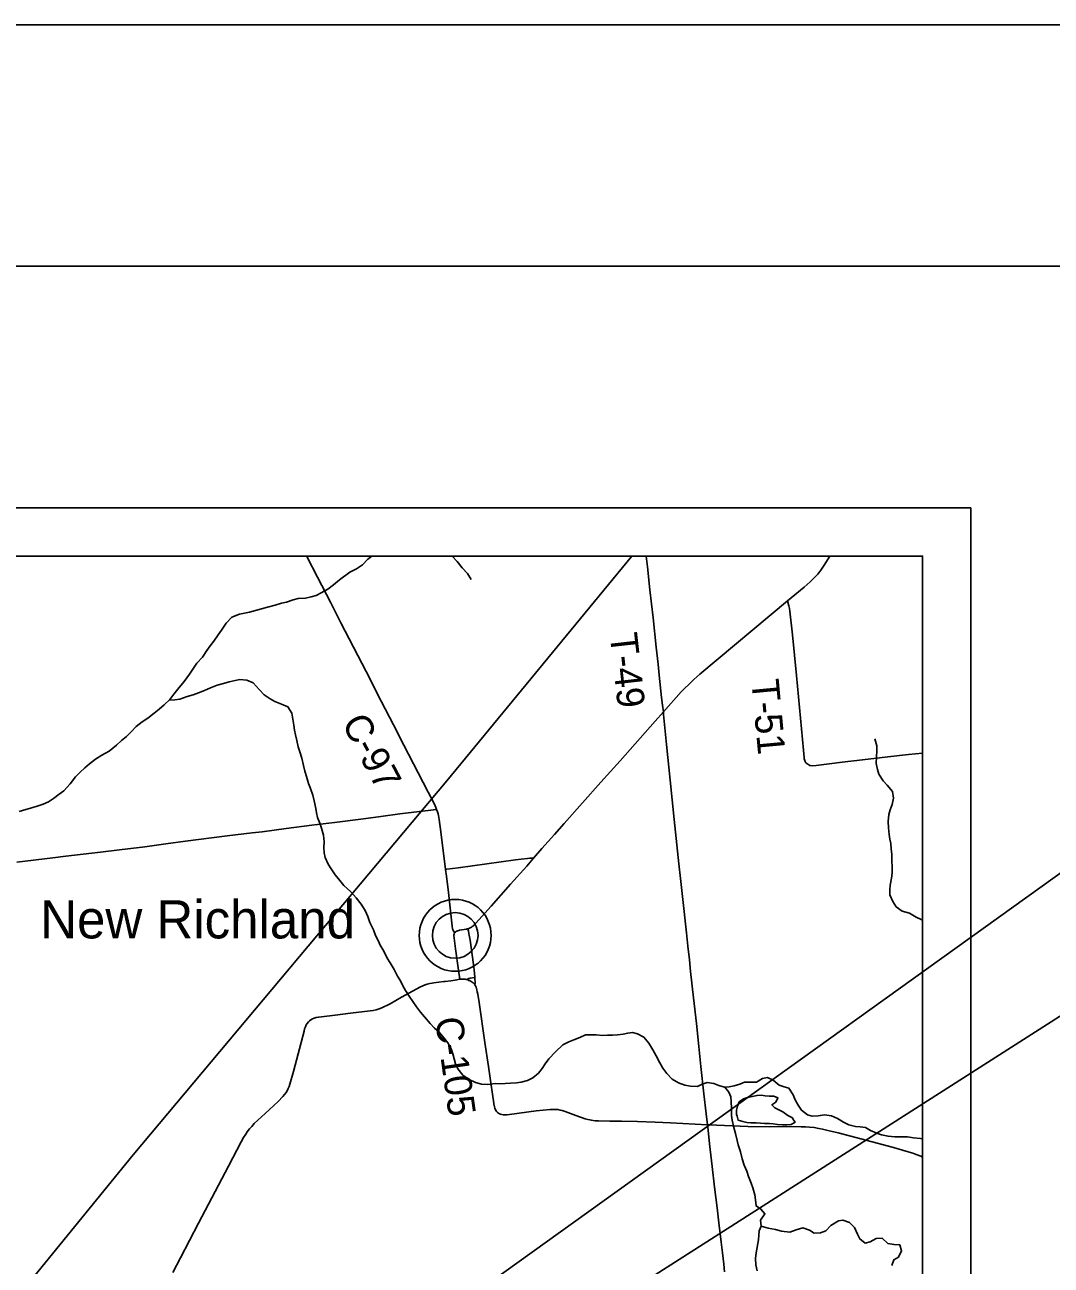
# Model space of a CAD drawing. Extents: x 0 to 34, y -5.4 to 22.
# Drawn here: x 7.042 to 9.166, y 19.432 to 22 of the extents above; entities that cross this region are included whole.
import ezdxf

# ---------------------------------------------------------------- set-up
doc = ezdxf.new("R2010")
doc.units = 0
for name, color, linetype in [('GM_X_County_Road', 7, 'Continuous'), ('GM_X_County_Road_Text', 7, 'Continuous'), ('GM_X_Minor_Lake', 7, 'Continuous'), ('GM_X_Minor_River', 7, 'Continuous'), ('GM_X_Rail_Line', 7, 'Continuous'), ('GM_X_Township_Road', 7, 'Continuous'), ('GM_X_Township_Road_Text', 7, 'Continuous'), ('GM_X_Unincorporated', 7, 'Continuous'), ('GM_X_Unincorporated_Location', 7, 'Continuous'), ('GM_X_Unincorporated_Text', 7, 'Continuous'), ('SH_Border', 7, 'Continuous'), ('SH_Cut_Line', 7, 'Continuous'), ('SH_Data', 7, 'Continuous')]:
    doc.layers.add(name, color=color, linetype=linetype)

msp = doc.modelspace()

# ---------------------------------------------------------------- linework, layer by layer
at = {"layer": 'GM_X_County_Road'}
for points in [[(7.8939, 20.3752), (7.8923, 20.3795), (7.8907, 20.3831), (7.8875, 20.3904), (7.8765, 20.4113), (7.8559, 20.451), (7.826, 20.5084), (7.8047, 20.5504), (7.7795, 20.5996), (7.748, 20.661), (7.6961, 20.7615), (7.6749, 20.803), (7.6478, 20.8561), (7.6264, 20.8976), (7.6252, 20.9)], [(7.912, 20.0194), (7.9236, 20.0208), (7.9322, 20.022), (7.9419, 20.0238), (7.9391, 20.043), (7.9329, 20.0867), (7.9299, 20.1146), (7.93, 20.1161), (7.9303, 20.1175), (7.9306, 20.1185), (7.9312, 20.1195), (7.9314, 20.1198), (7.9321, 20.1209), (7.9332, 20.122), (7.9347, 20.1231), (7.9361, 20.1237), (7.9378, 20.1243), (7.9397, 20.1248), (7.9417, 20.1252), (7.9561, 20.1278), (7.9574, 20.1281), (7.9588, 20.1286), (7.9606, 20.1292), (7.9623, 20.1299), (7.9647, 20.131), (7.9663, 20.1319), (7.9678, 20.1329), (7.9692, 20.134), (7.9708, 20.1353), (7.9719, 20.1363), (7.9755, 20.1397), (8.0067, 20.1751), (8.047, 20.2207), (8.0806, 20.2582), (8.0946, 20.2744), (8.1118, 20.2944), (8.1378, 20.3237), (8.1582, 20.3463), (8.234, 20.4318), (8.2738, 20.4763), (8.3462, 20.5582), (8.3634, 20.5775), (8.4005, 20.6188), (8.4079, 20.6264), (8.4158, 20.6344), (8.4264, 20.6443), (8.4389, 20.6552), (8.6206, 20.8074), (8.6278, 20.8135), (8.6546, 20.8357), (8.6672, 20.8468), (8.6762, 20.8555), (8.6829, 20.8629), (8.6891, 20.8708), (8.6962, 20.881), (8.7082, 20.9)], [(8.4901, 19.4183), (8.4882, 19.4341), (8.4855, 19.4577), (8.4829, 19.4798), (8.4783, 19.5193), (8.4745, 19.5507), (8.4694, 19.5933), (8.4644, 19.6359), (8.459, 19.6834), (8.4552, 19.7181), (8.4547, 19.7223), (8.452, 19.745), (8.447, 19.7867), (8.4407, 19.8432), (8.4365, 19.8846), (8.4316, 19.9322), (8.4258, 19.9853), (8.4198, 20.0396), (8.4172, 20.0643), (8.414, 20.0927), (8.4111, 20.1199), (8.4029, 20.1953), (8.3989, 20.2323), (8.3956, 20.2625), (8.3855, 20.3546), (8.3772, 20.4362), (8.3698, 20.5098), (8.3638, 20.5718), (8.3634, 20.5775)], [(7.025, 20.2661), (7.0994, 20.2752), (7.1265, 20.2784), (7.1981, 20.2868), (7.2376, 20.2915), (7.29, 20.298), (7.3337, 20.3041), (7.3744, 20.3095), (7.4607, 20.3205), (7.5125, 20.3271), (7.5328, 20.3294), (7.5581, 20.3326), (7.5827, 20.336), (7.6357, 20.3429), (7.6826, 20.3486), (7.743, 20.3562), (7.7788, 20.361), (7.8176, 20.3662), (7.8822, 20.3737), (7.8878, 20.3744), (7.8939, 20.3752)], [(7.9314, 20.1198), (7.9304, 20.1214), (7.9281, 20.1251), (7.9275, 20.1267), (7.9271, 20.1285), (7.9265, 20.134), (7.9185, 20.2038), (7.9143, 20.2373), (7.9124, 20.251), (7.9116, 20.2573), (7.9087, 20.2784), (7.9027, 20.3289), (7.8995, 20.3549), (7.898, 20.3629), (7.897, 20.3662), (7.8959, 20.3702), (7.8939, 20.3752)], [(7.9124, 20.251), (7.9154, 20.2515), (7.9387, 20.2549), (8.057, 20.2709), (8.0693, 20.2724), (8.0818, 20.2738), (8.0873, 20.2743), (8.0923, 20.2745), (8.0946, 20.2744)], [(7.716, 19.9536), (7.7568, 19.9585), (7.7625, 19.9595), (7.7689, 19.9609), (7.7753, 19.9628), (7.7806, 19.9647), (7.786, 19.9672), (7.7924, 19.9701), (7.7981, 19.9733), (7.8216, 19.9865), (7.8531, 20.0042), (7.8593, 20.0074), (7.8655, 20.0102), (7.8706, 20.0123), (7.8747, 20.0137), (7.8802, 20.0152), (7.8849, 20.0161), (7.8884, 20.0166), (7.9088, 20.019), (7.912, 20.0194)], [(7.9419, 20.0238), (7.9463, 20.024), (7.9494, 20.024), (7.9528, 20.0238), (7.9555, 20.0234), (7.9566, 20.0231), (7.9583, 20.0226), (7.9609, 20.0216), (7.9632, 20.0205), (7.9655, 20.0192), (7.9674, 20.018), (7.9698, 20.0162), (7.9716, 20.0145), (7.9728, 20.0128), (7.973, 20.0126), (7.9744, 20.0101), (7.9756, 20.0074), (7.9764, 20.0046), (7.9772, 20.0019), (7.9781, 19.9977), (7.979, 19.9932), (7.9819, 19.9756), (7.994, 19.8927), (8.0014, 19.843), (8.0058, 19.814), (8.0105, 19.7811), (8.0117, 19.7722), (8.0127, 19.7661), (8.014, 19.7596), (8.0148, 19.7568), (8.016, 19.7535), (8.017, 19.7516), (8.0182, 19.7499), (8.0197, 19.7482), (8.0218, 19.7466), (8.0239, 19.7455), (8.0265, 19.7443), (8.0291, 19.7437), (8.0316, 19.7432), (8.0356, 19.7431), (8.0392, 19.7433), (8.045, 19.7439), (8.1002, 19.7513), (8.1292, 19.7542), (8.135, 19.7545), (8.1403, 19.7543), (8.1447, 19.7539), (8.1494, 19.7531), (8.1542, 19.752), (8.1601, 19.7502), (8.1822, 19.7421), (8.2014, 19.7351), (8.2045, 19.734), (8.2073, 19.7332), (8.2109, 19.7325), (8.2144, 19.7318), (8.218, 19.7314), (8.2223, 19.731), (8.2293, 19.7305), (8.2523, 19.7299), (8.2765, 19.7299), (8.31, 19.7293), (8.3466, 19.7278), (8.3782, 19.7263), (8.4547, 19.7223), (8.4577, 19.7222), (8.5384, 19.7191), (8.5831, 19.7184), (8.6254, 19.7187), (8.6485, 19.7184), (8.6578, 19.718), (8.6658, 19.7176), (8.6755, 19.7166), (8.6849, 19.7151), (8.6927, 19.7135), (8.7036, 19.711), (8.7251, 19.7056), (8.7954, 19.6871), (8.8398, 19.6753), (8.8697, 19.6667), (8.8794, 19.6637), (8.8867, 19.6612), (8.8964, 19.6573), (8.9, 19.6557)], [(7.3483, 19.4166), (7.3639, 19.4471), (7.4015, 19.5187), (7.4359, 19.5841), (7.4634, 19.637), (7.4894, 19.6873), (7.4943, 19.6962), (7.499, 19.7034), (7.5022, 19.708), (7.507, 19.7145), (7.5113, 19.7192), (7.5167, 19.7251), (7.5391, 19.7459), (7.5662, 19.7705), (7.576, 19.7808), (7.5795, 19.7852), (7.5825, 19.7897), (7.5844, 19.7931), (7.5869, 19.7978), (7.5885, 19.8016), (7.5902, 19.8064), (7.5979, 19.8332), (7.6134, 19.8928), (7.6197, 19.9165), (7.6209, 19.9211), (7.6223, 19.9251), (7.6243, 19.9293), (7.6263, 19.9325), (7.6286, 19.9355), (7.6308, 19.9377), (7.634, 19.9401), (7.637, 19.9418), (7.6409, 19.9434), (7.645, 19.9447), (7.6501, 19.9456), (7.6556, 19.9464), (7.6841, 19.9498), (7.716, 19.9536)]]:
    msp.add_lwpolyline(points, dxfattribs=at)
at = {"layer": 'GM_X_Minor_Lake'}
for points in [[(8.6323, 19.7336), (8.6303, 19.7367), (8.6213, 19.7418), (8.6105, 19.7492), (8.6026, 19.7535), (8.5943, 19.7578), (8.5879, 19.7639), (8.5964, 19.7695), (8.6003, 19.7782), (8.592, 19.7821), (8.5825, 19.7815), (8.5742, 19.7827), (8.5655, 19.784), (8.5572, 19.7834), (8.5473, 19.7809), (8.5374, 19.7788), (8.529, 19.7762), (8.5202, 19.7699), (8.517, 19.7612), (8.5146, 19.7526), (8.5149, 19.7438)], [(8.5149, 19.7438), (8.516, 19.7404), (8.5185, 19.732), (8.5275, 19.7292), (8.5358, 19.7275), (8.5445, 19.7267), (8.5552, 19.7269), (8.5646, 19.726), (8.573, 19.7255), (8.5828, 19.7249), (8.5907, 19.7244), (8.5998, 19.7231), (8.6097, 19.7222), (8.6195, 19.7224), (8.6282, 19.7234), (8.6359, 19.7279), (8.6323, 19.7336)]]:
    msp.add_lwpolyline(points, dxfattribs=at)
at = {"layer": 'GM_X_Minor_River'}
for points in [[(7.0303, 20.371), (7.044, 20.3753), (7.0581, 20.3793), (7.0676, 20.3825), (7.0794, 20.3865), (7.0908, 20.3909), (7.1008, 20.3979), (7.1127, 20.4069), (7.1223, 20.4143), (7.1354, 20.4285), (7.1466, 20.4432), (7.1562, 20.4525), (7.1658, 20.4615), (7.1754, 20.4697), (7.188, 20.4793), (7.2014, 20.4879), (7.2163, 20.4964), (7.2317, 20.5083), (7.2421, 20.518), (7.2521, 20.5265), (7.262, 20.5359), (7.2725, 20.5471), (7.2847, 20.5568), (7.2962, 20.5646), (7.3093, 20.575), (7.32, 20.5832), (7.3304, 20.5921), (7.3419, 20.6033), (7.3504, 20.6138), (7.3585, 20.6243), (7.3713, 20.6404), (7.3825, 20.6558), (7.3906, 20.6682), (7.3976, 20.678), (7.4096, 20.6907), (7.4185, 20.7042), (7.4254, 20.714), (7.4332, 20.7241), (7.4417, 20.7369), (7.4491, 20.7466), (7.4584, 20.7609), (7.4699, 20.7737), (7.4863, 20.7798), (7.4962, 20.7816), (7.5069, 20.7841), (7.5194, 20.7873), (7.5316, 20.7909), (7.5438, 20.7941), (7.5601, 20.7984), (7.5727, 20.8024), (7.5833, 20.8049), (7.5971, 20.8096), (7.6073, 20.8125), (7.6225, 20.813), (7.6347, 20.8159), (7.6446, 20.8187), (7.6553, 20.8239), (7.669, 20.8313), (7.6805, 20.8406), (7.6932, 20.8506), (7.7146, 20.867), (7.7284, 20.8736), (7.7403, 20.8821), (7.7518, 20.8937), (7.7596, 20.9)], [(7.926, 20.9), (7.9363, 20.8886), (7.9471, 20.8759), (7.9579, 20.8643), (7.9653, 20.8517)], [(7.3404, 20.6018), (7.3525, 20.6024), (7.3628, 20.6041), (7.3776, 20.6096), (7.3902, 20.6128), (7.4012, 20.6168), (7.4134, 20.6216), (7.426, 20.6274), (7.4397, 20.6329), (7.4531, 20.6365), (7.4645, 20.6397), (7.477, 20.6422), (7.4865, 20.6443), (7.5009, 20.6434), (7.5141, 20.6375), (7.5264, 20.624), (7.5372, 20.6128), (7.5496, 20.6046), (7.5594, 20.5992), (7.5733, 20.5936), (7.5861, 20.5881), (7.5946, 20.5747), (7.5963, 20.5621), (7.5984, 20.55), (7.6001, 20.5397), (7.6019, 20.5298), (7.6044, 20.5184), (7.6076, 20.505), (7.6108, 20.4944), (7.6148, 20.4814), (7.6183, 20.4665), (7.6212, 20.4547), (7.6244, 20.4437), (7.6291, 20.4292), (7.6331, 20.4188), (7.6375, 20.4047), (7.6407, 20.3933), (7.6439, 20.3777), (7.6456, 20.3682), (7.6478, 20.3587), (7.6521, 20.3468), (7.6561, 20.3365), (7.6597, 20.322), (7.661, 20.3087), (7.6605, 20.297), (7.6614, 20.2856), (7.6636, 20.276), (7.6698, 20.2619), (7.6761, 20.2523), (7.6842, 20.24), (7.6935, 20.2281), (7.7017, 20.2177), (7.7159, 20.2054), (7.7275, 20.1927), (7.7382, 20.1796), (7.7464, 20.1662), (7.7515, 20.1536), (7.7555, 20.1417), (7.7632, 20.1264), (7.7676, 20.1142), (7.7731, 20.1039), (7.7775, 20.0943), (7.7849, 20.0817), (7.7915, 20.0675), (7.7978, 20.058), (7.8063, 20.0442), (7.8129, 20.0304), (7.8192, 20.0204), (7.8243, 20.0105), (7.8299, 20.0009), (7.8369, 19.9886), (7.8447, 19.9775), (7.8521, 19.9668), (7.861, 19.956), (7.8692, 19.946), (7.8804, 19.9325), (7.8897, 19.9225), (7.8994, 19.914), (7.9098, 19.9017), (7.9173, 19.8921), (7.9243, 19.8795), (7.9279, 19.8695), (7.9304, 19.8593), (7.9333, 19.8486), (7.9377, 19.8387), (7.9485, 19.8252), (7.9612, 19.8166), (7.9744, 19.8104), (7.9868, 19.8068), (8.0001, 19.8062), (8.0149, 19.8082), (8.0266, 19.8076), (8.0361, 19.8083), (8.0467, 19.8089), (8.0596, 19.8094), (8.0691, 19.8108), (8.0824, 19.8144), (8.0935, 19.8195), (8.1046, 19.8292), (8.1127, 19.8389), (8.119, 19.8487)], [(8.8007, 20.5214), (8.8054, 20.5069), (8.8052, 20.4967), (8.8043, 20.4846), (8.804, 20.4705), (8.8065, 20.4584), (8.809, 20.4485), (8.8182, 20.435), (8.8267, 20.4254), (8.8375, 20.4123), (8.8399, 20.3986), (8.8367, 20.3854), (8.8327, 20.3749), (8.8303, 20.365), (8.8289, 20.3506), (8.8294, 20.3377), (8.8307, 20.3237), (8.8321, 20.3142), (8.8338, 20.3047), (8.8351, 20.2933), (8.8361, 20.2826), (8.8362, 20.2686), (8.8368, 20.2572), (8.8369, 20.2436), (8.8356, 20.2333), (8.8331, 20.219), (8.8318, 20.2091), (8.8324, 20.1985), (8.8386, 20.1851), (8.8452, 20.174), (8.8579, 20.1651), (8.873, 20.1606), (8.8869, 20.1524), (8.897, 20.1477), (8.9, 20.1464)], [(8.119, 19.8487), (8.1263, 19.8592), (8.1398, 19.8734), (8.1556, 19.888), (8.1674, 19.8943), (8.1781, 19.8983), (8.1903, 19.9034), (8.2021, 19.9085), (8.212, 19.9091), (8.2245, 19.9089), (8.2377, 19.9076), (8.248, 19.9082), (8.2578, 19.9084), (8.2684, 19.9086), (8.2798, 19.9103), (8.2897, 19.9125), (8.2996, 19.9138), (8.3101, 19.9106), (8.3229, 19.9043), (8.3333, 19.8913), (8.3418, 19.8779), (8.3481, 19.8652), (8.3558, 19.8511), (8.3625, 19.84), (8.3703, 19.8285), (8.3818, 19.8169), (8.395, 19.8095), (8.4078, 19.8047), (8.4195, 19.8026), (8.4339, 19.802), (8.4435, 19.8068), (8.4541, 19.8104), (8.4677, 19.8083), (8.4783, 19.804), (8.4896, 19.8004), (8.4995, 19.8014), (8.5097, 19.8031), (8.5215, 19.8067), (8.5311, 19.8108), (8.5428, 19.8109), (8.5561, 19.8111), (8.5687, 19.8185), (8.5786, 19.8203), (8.5906, 19.8148), (8.6033, 19.8047), (8.6131, 19.8011), (8.6233, 19.7983), (8.6318, 19.7849), (8.6362, 19.7742), (8.6421, 19.7635), (8.6492, 19.7531), (8.6615, 19.743), (8.6713, 19.7406), (8.6835, 19.7412), (8.6968, 19.7429), (8.7111, 19.7411), (8.7235, 19.7356), (8.7363, 19.7278), (8.7472, 19.7223), (8.7608, 19.7191), (8.771, 19.7185), (8.7816, 19.7169), (8.7918, 19.7106), (8.8053, 19.7051), (8.8151, 19.7019), (8.8283, 19.6987), (8.8423, 19.6977), (8.8564, 19.6979), (8.8685, 19.6973), (8.8813, 19.6956), (8.8953, 19.6942), (8.9, 19.6935)], [(8.4909, 19.8005), (8.4985, 19.7904), (8.5033, 19.7804), (8.5039, 19.7709), (8.5041, 19.7565), (8.5046, 19.7417), (8.506, 19.7318), (8.5092, 19.7166), (8.5124, 19.7048), (8.5163, 19.6903), (8.5185, 19.6808), (8.5228, 19.6666), (8.5264, 19.6522), (8.5307, 19.6392), (8.5362, 19.6266), (8.5394, 19.6155), (8.5449, 19.6014), (8.5485, 19.5918), (8.5529, 19.5774), (8.5539, 19.5671), (8.5552, 19.5545), (8.5653, 19.5479), (8.5735, 19.5379), (8.5642, 19.5248), (8.5655, 19.5126), (8.5802, 19.5086), (8.5957, 19.5057), (8.6078, 19.5021), (8.6252, 19.4999), (8.6382, 19.5054), (8.6519, 19.509), (8.6658, 19.5042), (8.6756, 19.4984), (8.6885, 19.4989), (8.6995, 19.5033), (8.7103, 19.5142), (8.7256, 19.5238), (8.7351, 19.5248), (8.7483, 19.5204), (8.7587, 19.5096), (8.7654, 19.4962), (8.7701, 19.4863), (8.781, 19.4777), (8.7916, 19.4802), (8.8039, 19.4873), (8.8164, 19.4878), (8.828, 19.477), (8.8408, 19.4745), (8.8526, 19.474), (8.8565, 19.4614), (8.8499, 19.4486), (8.8403, 19.443), (8.8364, 19.4313)], [(8.5657, 19.5126), (8.5616, 19.5032), (8.5607, 19.4937), (8.5605, 19.4842), (8.5556, 19.4577), (8.5543, 19.4456), (8.5548, 19.4327), (8.5577, 19.4201)]]:
    msp.add_lwpolyline(points, dxfattribs=at)
at = {"layer": 'GM_X_Rail_Line'}
msp.add_lwpolyline([(8.9, 19.2127), (8.9, 20.9), (3.5133, 20.9), (3.5122, 20.8763), (3.4778, 20.1697), (3.46, 19.8188), (3.4303, 19.2337), (3.4301, 19.2311), (3.4297, 19.2264), (3.3865, 18.7781), (3.3669, 18.5872), (3.5131, 18.6037), (4.7505, 18.7432), (5.0255, 18.7742), (5.096, 18.7806), (5.378, 18.814), (5.7313, 18.8595), (5.7334, 18.8597), (6.0045, 18.8908), (6.4496, 18.9373), (6.6792, 18.9603), (6.9054, 18.9823), (7.2315, 19.0156), (8.5201, 19.1691)], close=True, dxfattribs=at)
msp.add_lwpolyline([(8.2982, 20.9), (7.9149, 20.4347), (7.2657, 19.6601), (6.962, 19.2874), (6.9019, 19.2104), (6.8655, 19.1557), (6.8321, 19.1035), (6.789, 19.0121), (6.7581, 18.9233), (6.7239, 18.8129), (6.4727, 18.0601), (6.244, 17.3648), (6.1298, 17.0307)], dxfattribs=at)
at = {"layer": 'GM_X_Township_Road'}
for points in [[(8.3634, 20.5775), (8.3615, 20.5916), (8.3596, 20.6069), (8.3546, 20.6533), (8.3523, 20.6761), (8.3487, 20.7114), (8.3419, 20.7719), (8.3355, 20.8299), (8.3302, 20.8781), (8.3278, 20.9)], [(8.6206, 20.8074), (8.6231, 20.7968), (8.6241, 20.7916), (8.625, 20.7861), (8.6303, 20.7373), (8.6386, 20.6526), (8.6534, 20.4979), (8.6546, 20.483), (8.6551, 20.4803), (8.656, 20.4768), (8.6571, 20.4744), (8.6585, 20.4721), (8.6602, 20.4703), (8.6621, 20.4689), (8.6641, 20.4676), (8.6663, 20.4667), (8.6679, 20.4663), (8.671, 20.466), (8.6799, 20.4666), (8.7336, 20.4735), (8.7756, 20.4785), (8.8281, 20.4844), (8.8707, 20.489), (8.9, 20.492)], [(7.9728, 20.0128), (7.9733, 20.0147), (7.9735, 20.0161), (7.9736, 20.0177), (7.9736, 20.0196), (7.9734, 20.0227), (7.973, 20.028), (7.9725, 20.036), (7.9717, 20.0437), (7.9705, 20.0544), (7.9634, 20.1048), (7.961, 20.1189), (7.9601, 20.1236), (7.9589, 20.1283)], [(7.9566, 20.0231), (7.9578, 20.0239), (7.959, 20.0246), (7.9602, 20.0252), (7.9618, 20.0257), (7.9635, 20.0261), (7.9721, 20.0278), (7.973, 20.028)]]:
    msp.add_lwpolyline(points, dxfattribs=at)
at = {"layer": 'GM_X_Unincorporated'}
for radius in [0.0744, 0.0472]:
    msp.add_circle((7.9325, 20.1147), radius, dxfattribs=at)
at = {"layer": 'GM_X_Unincorporated_Location'}
msp.add_line((7.9325, 20.1147), (7.9325, 20.1147), dxfattribs=at)
at = {"layer": 'SH_Border'}
msp.add_lwpolyline([(1.5, 21.5), (33.5, 21.5), (33.5, 0.5), (1.5, 0.5)], close=True, dxfattribs=at)
at = {"layer": 'SH_Cut_Line'}
msp.add_lwpolyline([(0, 0), (34, 0), (34, 22), (0, 22)], close=True, dxfattribs=at)
at = {"layer": 'SH_Data'}
for p, q in [((2, 21), (9, 21)), ((9, 21), (9, 14)), ((2.1, 20.9), (8.9, 20.9)), ((8.9, 20.9), (8.9, 14.1))]:
    msp.add_line(p, q, dxfattribs=at)
msp.add_lwpolyline([(9.2327, 20.2782), (5.4298, 17.5482), (9.2327, 19.9788)], close=True, dxfattribs=at)

# ---------------------------------------------------------------- texts
at = {"layer": 'GM_X_County_Road_Text'}
for s, rotation, p in [('C-97', 297.7886, (7.6966, 20.5549)), ('C-105', 278.0141, (7.8908, 19.9422))]:
    msp.add_text(s, height=0.05682, rotation=rotation, dxfattribs=at).set_placement(p)
at = {"layer": 'GM_X_Township_Road_Text'}
for s, rotation, p in [('T-49', 276.3798, (8.2522, 20.7383)), ('T-51', 275.2899, (8.5453, 20.6427))]:
    msp.add_text(s, height=0.05682, rotation=rotation, dxfattribs=at).set_placement(p)
at = {"layer": 'GM_X_Unincorporated_Text'}
msp.add_text('New Richland', height=0.078977, rotation=0, dxfattribs=at).set_placement((7.0735, 20.1084))

doc.saveas('drawing.dxf')
